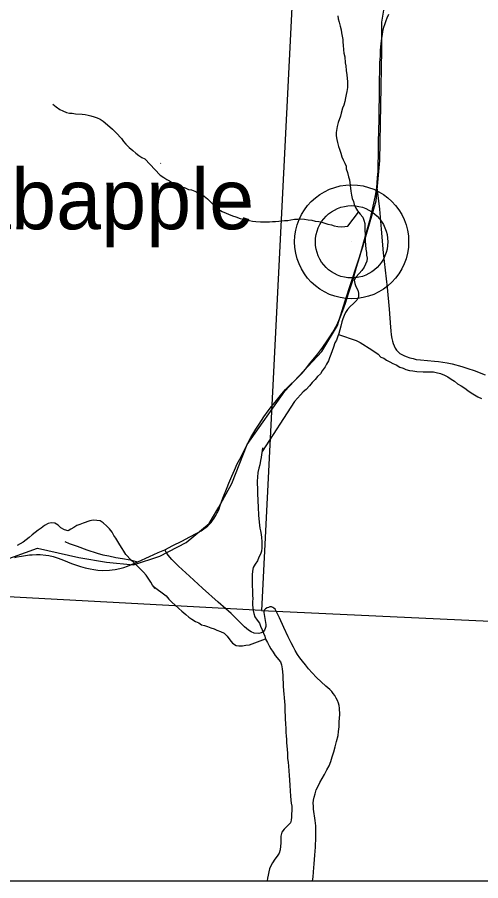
# Model space of a CAD drawing. Extents: x -3.3 to 34, y 0 to 56.8.
# Drawn here: x 2.263 to 2.868, y 28.077 to 29.204 of the extents above; entities that cross this region are included whole.
import ezdxf

# ---------------------------------------------------------------- set-up
doc = ezdxf.new("R2010")
doc.units = 0
for name, color, linetype in [('GM_X_Corporation', 7, 'Continuous'), ('GM_X_Rail_Line', 7, 'Continuous'), ('GM_X_Township_Road', 7, 'Continuous'), ('GM_X_Unincorporated', 7, 'Continuous'), ('GM_X_Unincorporated_Location', 7, 'Continuous'), ('GM_X_Unincorporated_Text', 7, 'Continuous'), ('GT_Project_Soil_Layers', 7, 'Continuous'), ('SH_Data', 7, 'Continuous')]:
    doc.layers.add(name, color=color, linetype=linetype)

msp = doc.modelspace()

# ---------------------------------------------------------------- linework, layer by layer
at = {"layer": 'GM_X_Corporation'}
msp.add_lwpolyline([(1.7459, 32.363), (1.698, 31.5661), (1.6885, 31.0075), (1.6883, 30.9953), (1.6882, 30.9891), (1.685, 30.798), (1.6538, 30.0279), (1.6459, 29.8169), (1.5942, 28.7382), (1.5699, 28.0771), (3.4961, 28.0771)], dxfattribs=at)
for points in [[(1.6326, 29.488), (2.6327, 29.4334), (2.5822, 28.4298), (1.5887, 28.4831), (1.5929, 28.5794)], [(3.4961, 28.387), (3.4961, 29.3918), (2.6327, 29.4334), (2.5822, 28.4298)]]:
    msp.add_lwpolyline(points, close=True, dxfattribs=at)
at = {"layer": 'GM_X_Rail_Line'}
msp.add_lwpolyline([(2.2428, 28.4939), (2.2897, 28.5109), (2.3437, 28.4991), (2.3801, 28.4928), (2.4151, 28.4893), (2.4497, 28.5006), (2.484, 28.5184), (2.514, 28.5434), (2.5266, 28.5647), (2.5434, 28.5954), (2.5636, 28.6464), (2.6125, 28.716), (2.6608, 28.7679), (2.6813, 28.8018), (2.6914, 28.834), (2.7145, 28.9045), (2.732, 28.9642), (2.7368, 29.0171), (2.7394, 29.1613), (2.7394, 29.1977), (2.7417, 29.2132)], dxfattribs=at)
at = {"layer": 'GM_X_Township_Road'}
for points in [[(2.2601, 28.4988), (2.2635, 28.4997), (2.2688, 28.5008), (2.2741, 28.5017), (2.2795, 28.5023), (2.2831, 28.5025), (2.2886, 28.5027), (2.2933, 28.5026), (2.3006, 28.502), (2.3046, 28.5014), (2.3103, 28.5002), (2.317, 28.498), (2.324, 28.4955), (2.3343, 28.4912), (2.3408, 28.4888), (2.3462, 28.4871), (2.3521, 28.4855), (2.3586, 28.4841), (2.3636, 28.4831), (2.3684, 28.4825), (2.3743, 28.482), (2.3839, 28.4822), (2.3875, 28.4826), (2.3911, 28.4831), (2.3971, 28.4844), (2.4026, 28.486), (2.4073, 28.4876), (2.4206, 28.4933), (2.4359, 28.5001), (2.4473, 28.5053), (2.456, 28.5091), (2.4666, 28.5145), (2.4783, 28.5202), (2.4888, 28.5258), (2.4969, 28.5303), (2.5033, 28.5338), (2.5071, 28.5363), (2.5095, 28.5381), (2.512, 28.5401), (2.5142, 28.5422), (2.5163, 28.5446), (2.5184, 28.5471), (2.5206, 28.5504), (2.5228, 28.5538), (2.5245, 28.557), (2.5263, 28.5612), (2.5284, 28.5666), (2.5319, 28.5763), (2.5373, 28.5901), (2.5396, 28.5959), (2.5435, 28.6052), (2.5468, 28.613), (2.5506, 28.6212), (2.5555, 28.6304), (2.5616, 28.6431), (2.5684, 28.6553), (2.5749, 28.6663), (2.579, 28.6728), (2.5854, 28.6823), (2.591, 28.6901), (2.5954, 28.6958), (2.6017, 28.7038), (2.6085, 28.7124), (2.6137, 28.7182), (2.6193, 28.724), (2.6265, 28.7307), (2.6306, 28.7346), (2.6347, 28.739), (2.6397, 28.7446), (2.6453, 28.752), (2.6555, 28.7649), (2.6621, 28.7735), (2.6678, 28.7818), (2.672, 28.788), (2.6752, 28.7931), (2.6792, 28.8001), (2.6817, 28.8052), (2.6854, 28.8136), (2.6884, 28.8213), (2.6917, 28.8308), (2.6957, 28.8434), (2.7014, 28.8605), (2.7063, 28.8776), (2.7104, 28.8917), (2.7158, 28.9109), (2.7211, 28.9295), (2.7243, 28.9417), (2.7272, 28.9533), (2.7298, 28.9654), (2.7308, 28.9714), (2.7325, 28.9815), (2.7331, 28.9878), (2.7337, 28.9949), (2.7342, 29.0027), (2.7346, 29.0122), (2.7347, 29.024), (2.735, 29.0424), (2.7351, 29.0549), (2.7355, 29.0718), (2.7361, 29.1114), (2.7368, 29.1444), (2.7373, 29.1534), (2.7376, 29.1607), (2.7384, 29.1698), (2.7392, 29.1765), (2.7399, 29.1813), (2.7406, 29.1853), (2.7419, 29.1909), (2.743, 29.1944), (2.7448, 29.1996), (2.7462, 29.203), (2.7484, 29.208)], [(2.7325, 28.9815), (2.7344, 28.9679), (2.7361, 28.9537), (2.7385, 28.9273), (2.7409, 28.8967), (2.7434, 28.874), (2.7461, 28.8513), (2.7486, 28.8231), (2.7507, 28.7993), (2.7509, 28.7949), (2.7515, 28.7896), (2.7521, 28.7847), (2.7531, 28.7813), (2.7542, 28.7782), (2.7553, 28.775), (2.7568, 28.7723), (2.7584, 28.7697), (2.7604, 28.7674), (2.7628, 28.7653), (2.7654, 28.7637), (2.7679, 28.7624), (2.7711, 28.761), (2.7756, 28.7596), (2.78, 28.7584), (2.7842, 28.7575), (2.7897, 28.7568), (2.8081, 28.7551), (2.8133, 28.7546), (2.8189, 28.7538), (2.8246, 28.7529), (2.831, 28.7515), (2.8434, 28.7481), (2.8516, 28.7456), (2.8597, 28.7429), (2.8742, 28.7372)], [(2.3255, 28.5196), (2.3314, 28.5171), (2.3417, 28.5135), (2.3544, 28.509), (2.3679, 28.5047), (2.3753, 28.5025), (2.3829, 28.5009), (2.392, 28.4991), (2.4009, 28.4975), (2.4106, 28.4957), (2.4154, 28.4947), (2.4206, 28.4933)], [(2.6489, 28.0771), (2.6495, 28.0818), (2.6502, 28.0885), (2.6509, 28.0992), (2.6519, 28.1102), (2.6528, 28.1207), (2.6532, 28.134), (2.653, 28.1488), (2.6523, 28.1556), (2.6502, 28.1704), (2.6499, 28.1742), (2.6498, 28.1783), (2.65, 28.1821), (2.6508, 28.1863), (2.652, 28.1906), (2.6537, 28.1955), (2.656, 28.2003), (2.6583, 28.2051), (2.6613, 28.2105), (2.6642, 28.2158), (2.6675, 28.2216), (2.6704, 28.2271), (2.6727, 28.2328), (2.6746, 28.2386), (2.6764, 28.2452), (2.6782, 28.2516), (2.6802, 28.2588), (2.6821, 28.2665), (2.6828, 28.272), (2.6835, 28.278), (2.6837, 28.2844), (2.6843, 28.294), (2.6841, 28.3024), (2.6836, 28.3056), (2.6825, 28.3089), (2.6812, 28.3123), (2.6797, 28.3155), (2.6779, 28.3187), (2.6759, 28.3214), (2.6738, 28.3239), (2.6712, 28.3265), (2.6663, 28.331), (2.6599, 28.3367), (2.6541, 28.3423), (2.6484, 28.3483), (2.6434, 28.3538), (2.6394, 28.3588), (2.6355, 28.3634), (2.6322, 28.368), (2.6293, 28.3724), (2.6262, 28.3777), (2.6238, 28.382), (2.6208, 28.3874), (2.617, 28.3955), (2.6112, 28.4076), (2.6055, 28.42), (2.6014, 28.4289), (2.5999, 28.4316), (2.5983, 28.4329), (2.5968, 28.4337), (2.5951, 28.4343), (2.5932, 28.4343), (2.5914, 28.4338), (2.5896, 28.433), (2.5875, 28.432), (2.5866, 28.4311), (2.5858, 28.4301), (2.5854, 28.429), (2.5852, 28.4271), (2.5875, 28.414), (2.5878, 28.4113), (2.5877, 28.4089), (2.587, 28.4063), (2.586, 28.4041), (2.5843, 28.402), (2.5816, 28.4005), (2.5785, 28.3996), (2.5725, 28.4003), (2.5689, 28.4019), (2.5653, 28.4039), (2.5601, 28.4083), (2.5523, 28.4163), (2.5428, 28.426), (2.5357, 28.4321), (2.5258, 28.4408), (2.5054, 28.4587), (2.4884, 28.4744), (2.4739, 28.4878), (2.4653, 28.4964), (2.4602, 28.5021), (2.4577, 28.5058), (2.456, 28.5091)]]:
    msp.add_lwpolyline(points, dxfattribs=at)
at = {"layer": 'GM_X_Unincorporated'}
for radius in [0.0744, 0.0472]:
    msp.add_circle((2.6998, 28.9109), radius, dxfattribs=at)
at = {"layer": 'GM_X_Unincorporated_Location'}
msp.add_line((2.6998, 28.9109), (2.6998, 28.9109), dxfattribs=at)
at = {"layer": 'GT_Project_Soil_Layers'}
for points in [[(2.6816, 29.2058), (2.6821, 29.202), (2.6837, 29.1975), (2.6849, 29.1922), (2.6861, 29.1876), (2.6865, 29.1838), (2.6873, 29.1793), (2.6881, 29.1751), (2.6885, 29.1713), (2.6886, 29.1675), (2.6891, 29.1615), (2.6895, 29.1569), (2.6907, 29.1524), (2.6915, 29.1444), (2.6924, 29.1407), (2.6928, 29.1346), (2.6936, 29.1289), (2.6945, 29.1198), (2.6946, 29.116), (2.6942, 29.1122), (2.6936, 29.1069), (2.6928, 29.1031), (2.6918, 29.0989), (2.6907, 29.094), (2.6896, 29.0894), (2.6878, 29.0852), (2.6863, 29.0787), (2.6852, 29.0749), (2.6823, 29.0665), (2.6808, 29.0612), (2.6794, 29.0536), (2.6795, 29.049), (2.6803, 29.0445), (2.6815, 29.0403), (2.6827, 29.0354), (2.6839, 29.0317), (2.6855, 29.0264), (2.6871, 29.0218), (2.6886, 29.0177), (2.691, 29.0135), (2.6925, 29.0098), (2.6926, 29.006), (2.6945, 29.0014), (2.6957, 28.9958), (2.6969, 28.9916), (2.6986, 28.9768), (2.6995, 28.9719), (2.7007, 28.9674), (2.7022, 28.9636), (2.703, 28.9598), (2.705, 28.9557), (2.7073, 28.9515), (2.7108, 28.947), (2.7143, 28.9429), (2.7158, 28.9391), (2.717, 28.935), (2.7173, 28.9118), (2.7178, 28.9069), (2.7182, 28.9012), (2.719, 28.897), (2.7191, 28.8933), (2.7199, 28.8895), (2.7196, 28.8857), (2.7177, 28.8819), (2.7162, 28.8777), (2.7129, 28.8734), (2.7095, 28.8696), (2.7054, 28.8646)], [(2.3101, 29.0904), (2.3143, 29.087), (2.3189, 29.0837), (2.3228, 29.0818), (2.3277, 29.0796), (2.3315, 29.0789), (2.3353, 29.0786), (2.3395, 29.0779), (2.3482, 29.0773), (2.352, 29.0769), (2.3558, 29.0762), (2.3596, 29.0751), (2.3638, 29.0741), (2.3676, 29.0726), (2.3718, 29.0711), (2.3756, 29.0685), (2.3841, 29.0611), (2.3879, 29.0581), (2.3925, 29.0532), (2.3995, 29.0457), (2.4022, 29.042), (2.4052, 29.0382), (2.4095, 29.0341), (2.4141, 29.03), (2.4183, 29.0266), (2.4221, 29.0236), (2.4259, 29.021), (2.4298, 29.0192)], [(2.4298, 29.0192), (2.45, 28.9978), (2.4546, 28.9948), (2.4585, 28.9922), (2.4623, 28.9904), (2.4661, 28.9878), (2.4699, 28.9863), (2.4741, 28.9848), (2.478, 28.9826), (2.4825, 28.9812), (2.4871, 28.9793), (2.4909, 28.9786), (2.4951, 28.9772), (2.4989, 28.9749), (2.5035, 28.9735), (2.5074, 28.9705), (2.5116, 28.9671), (2.515, 28.9634), (2.5193, 28.9596), (2.5223, 28.9559), (2.5266, 28.9529), (2.5308, 28.9503), (2.5445, 28.9448), (2.5487, 28.9433), (2.5544, 28.9415), (2.5582, 28.9404), (2.562, 28.9397), (2.5666, 28.9386), (2.5704, 28.9379), (2.5746, 28.9376), (2.5807, 28.9369), (2.5928, 28.9371), (2.5966, 28.9375), (2.6004, 28.9376), (2.6046, 28.938), (2.6084, 28.9381), (2.6122, 28.9389), (2.6164, 28.9389), (2.6205, 28.9397), (2.6254, 28.9406), (2.6296, 28.9406), (2.6334, 28.9407), (2.6384, 28.9404), (2.6429, 28.9397), (2.6479, 28.939), (2.6524, 28.9379), (2.657, 28.9372), (2.6608, 28.9365), (2.6646, 28.9354), (2.6688, 28.9339), (2.6734, 28.9329), (2.6772, 28.9318), (2.6818, 28.9307), (2.686, 28.9304), (2.6909, 28.9308), (2.6947, 28.9313), (2.7089, 28.9495)], [(2.4505, 29.0133), (2.4506, 29.0134)], [(2.7054, 28.8646), (2.7032, 28.8608), (2.704, 28.8563), (2.7052, 28.8525), (2.7079, 28.848), (2.7087, 28.8438), (2.7088, 28.8392), (2.7065, 28.8347), (2.7024, 28.8304), (2.6979, 28.8266), (2.6946, 28.8227), (2.6919, 28.8185), (2.6901, 28.8147), (2.6883, 28.8105), (2.6868, 28.8063), (2.6857, 28.801), (2.6843, 28.796), (2.6832, 28.7911), (2.6813, 28.7865), (2.6799, 28.7827), (2.678, 28.7789), (2.6762, 28.7735), (2.6744, 28.7686), (2.6725, 28.764), (2.6711, 28.7594), (2.6696, 28.7556), (2.667, 28.7514), (2.6651, 28.7476), (2.6614, 28.7426), (2.6592, 28.7388), (2.6554, 28.7353), (2.6524, 28.7311), (2.6483, 28.7273), (2.645, 28.723), (2.6405, 28.7181), (2.6367, 28.715), (2.633, 28.7111), (2.6292, 28.7069), (2.6251, 28.7027), (2.583, 28.6374)], [(2.6828, 28.7901), (2.7057, 28.7823), (2.7111, 28.7793), (2.726, 28.77), (2.7344, 28.7641), (2.7379, 28.7603), (2.7417, 28.7589), (2.7455, 28.7563), (2.7497, 28.7544), (2.7536, 28.7522), (2.7578, 28.7504), (2.7627, 28.7474), (2.7669, 28.7459), (2.7707, 28.7441), (2.7753, 28.743), (2.7795, 28.7423), (2.7848, 28.7416), (2.7932, 28.741), (2.8065, 28.7411), (2.8103, 28.7404), (2.8156, 28.739), (2.821, 28.7368), (2.8252, 28.7346), (2.8298, 28.7316), (2.834, 28.729), (2.8378, 28.7256), (2.8428, 28.723), (2.8474, 28.7197), (2.8512, 28.7167), (2.8558, 28.7137), (2.86, 28.7111), (2.8646, 28.7085), (2.8692, 28.7063)], [(2.5834, 28.6421), (2.5831, 28.6379), (2.5823, 28.6333), (2.5816, 28.6295), (2.5809, 28.6254), (2.5798, 28.62), (2.5787, 28.6155), (2.5776, 28.6098), (2.5769, 28.6037), (2.5766, 28.5984), (2.5766, 28.5946), (2.577, 28.5896), (2.5771, 28.5798), (2.5775, 28.576), (2.5777, 28.5615), (2.5781, 28.5574), (2.5781, 28.5536), (2.5785, 28.5498), (2.5793, 28.5452), (2.5802, 28.5373), (2.581, 28.5335), (2.5818, 28.5289), (2.5822, 28.5248), (2.5826, 28.5198), (2.5827, 28.5115), (2.582, 28.5073), (2.5809, 28.5031), (2.5786, 28.4993), (2.5768, 28.4947), (2.5738, 28.4901), (2.5712, 28.4859), (2.5704, 28.481), (2.5701, 28.4764), (2.5698, 28.4726), (2.5702, 28.4685), (2.5703, 28.4495), (2.5708, 28.4453), (2.5704, 28.4411), (2.5705, 28.4373), (2.5713, 28.4298), (2.5721, 28.4256), (2.5736, 28.4214), (2.5767, 28.4173), (2.5794, 28.4131), (2.5809, 28.4094), (2.5829, 28.4044), (2.5848, 28.4003), (2.5864, 28.3961), (2.5875, 28.3923), (2.5899, 28.3878), (2.5922, 28.3837), (2.5945, 28.3799), (2.5976, 28.3754), (2.5999, 28.3712), (2.6068, 28.3629), (2.6083, 28.3588), (2.6091, 28.3538), (2.61, 28.3455), (2.61, 28.3406), (2.6104, 28.3349), (2.6105, 28.3311), (2.6109, 28.3254), (2.6113, 28.3205), (2.6117, 28.3163), (2.6122, 28.3106), (2.6126, 28.3068), (2.6127, 28.2973), (2.6131, 28.2928), (2.6131, 28.2878), (2.6136, 28.2821), (2.614, 28.2753), (2.614, 28.2711), (2.6145, 28.2658), (2.6149, 28.262), (2.6149, 28.2571), (2.6153, 28.2529), (2.6162, 28.2434), (2.6162, 28.237), (2.617, 28.2313), (2.6175, 28.2271), (2.6179, 28.2199), (2.6183, 28.215), (2.6192, 28.2017), (2.6197, 28.1938), (2.6201, 28.1877), (2.6205, 28.1824), (2.6209, 28.1782), (2.6217, 28.1744), (2.6218, 28.1687), (2.6214, 28.1638), (2.6215, 28.16), (2.6208, 28.1562), (2.62, 28.1524), (2.6163, 28.1485), (2.6118, 28.1443), (2.6088, 28.1405), (2.6073, 28.1352), (2.6074, 28.1264), (2.6067, 28.1173), (2.6052, 28.1131), (2.6026, 28.1089)], [(2.4434, 28.4584), (2.44, 28.4626), (2.4377, 28.4667), (2.4315, 28.4758), (2.4284, 28.4796), (2.4246, 28.4833), (2.4203, 28.4878), (2.4161, 28.492), (2.4123, 28.4954), (2.4053, 28.5029), (2.4026, 28.5071), (2.4003, 28.5108), (2.3972, 28.5154), (2.3949, 28.5199), (2.3922, 28.5241), (2.3895, 28.5278), (2.3872, 28.532), (2.3837, 28.5362), (2.3802, 28.5399), (2.3756, 28.5441), (2.3718, 28.5467), (2.3672, 28.5474), (2.3627, 28.5477), (2.3581, 28.5466), (2.3494, 28.5438), (2.3452, 28.5419), (2.3414, 28.5407), (2.3372, 28.538), (2.3334, 28.5357), (2.3297, 28.5337), (2.3251, 28.5348), (2.3205, 28.5375), (2.317, 28.5412), (2.3124, 28.5438), (2.3078, 28.5442), (2.304, 28.5434), (2.2991, 28.5407), (2.2946, 28.5372), (2.2908, 28.5345), (2.287, 28.5314), (2.2829, 28.5283), (2.2791, 28.5249), (2.2749, 28.5218), (2.2711, 28.5191), (2.2673, 28.5168), (2.2632, 28.5145)], [(2.4407, 28.4617), (2.4578, 28.4487), (2.4612, 28.4446), (2.465, 28.4408), (2.4696, 28.4367), (2.4742, 28.4322), (2.4784, 28.4288), (2.4834, 28.4243), (2.4872, 28.4209), (2.4914, 28.4183), (2.496, 28.4153), (2.5002, 28.4135), (2.504, 28.4112), (2.5078, 28.4101), (2.5116, 28.4087), (2.5161, 28.4072), (2.5203, 28.4057), (2.5241, 28.4042), (2.5287, 28.4024), (2.5333, 28.4001), (2.5375, 28.3964), (2.5409, 28.3915), (2.5444, 28.387), (2.5489, 28.384), (2.5527, 28.3836), (2.5573, 28.3837), (2.5618, 28.3845), (2.5664, 28.3849), (2.5874, 28.3927)], [(2.6026, 28.1089), (2.5996, 28.1051), (2.5966, 28.1005), (2.5944, 28.0963), (2.5925, 28.0925), (2.5918, 28.0887), (2.5907, 28.0841), (2.59, 28.0803), (2.5895, 28.0771)]]:
    msp.add_lwpolyline(points, dxfattribs=at)
at = {"layer": 'SH_Data'}
msp.add_line((-3.3039, 28.0771), (3.4961, 28.0771), dxfattribs=at)

# ---------------------------------------------------------------- texts
at = {"layer": 'GM_X_Unincorporated_Text'}
msp.add_text('Crabapple', height=0.07898, rotation=0, dxfattribs=at).set_placement((2.0853, 28.9273))

doc.saveas('drawing.dxf')
